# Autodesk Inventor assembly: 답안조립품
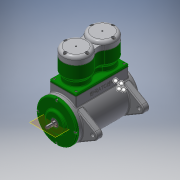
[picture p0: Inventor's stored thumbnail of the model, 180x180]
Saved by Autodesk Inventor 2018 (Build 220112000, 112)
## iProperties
Created: 2019-08
Part Number: 답안조립품
Document SubType Name: Assembly
Designer: Administrator
Mass: 7632.99 g
Surface Area: 5241.59 cm^2
Volume: 2149.87 cm^3
Density: 3.55045 g/cm^3
Author: Administrator
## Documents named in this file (18)
- C:\Users\Administrator\Desktop\1\답안조립품.iam
- C:\Users\Administrator\Desktop\1\본체.ipt
- C:\Users\Administrator\Desktop\1\실린더 개스킷.ipt
- C:\Users\Administrator\Desktop\1\실린더.ipt
- C:\Users\Administrator\Desktop\1\실린더헤드 개스킷.ipt
- C:\Users\Administrator\Desktop\1\실린더헤드.ipt
- C:\Users\Administrator\Desktop\1\볼트 M4 x 8.ipt
- C:\Users\Administrator\Desktop\1\볼트 M5 x 20.ipt
- C:\Users\Administrator\Desktop\1\너트 M4.ipt
- C:\Users\Administrator\Desktop\1\육각 머리 볼트 M4 x 16.ipt
- C:\Users\Administrator\Desktop\1\커넥팅로드.ipt
- C:\Users\Administrator\Desktop\1\피스톤.ipt
- C:\Users\Administrator\Desktop\1\피스톤핀.ipt
- C:\Users\Administrator\Desktop\1\커넥팅로드 엔드.ipt
- C:\Users\Administrator\Desktop\1\베어링 12 x 28 x 8.ipt
- C:\Users\Administrator\Desktop\1\앞커버.ipt
- C:\Users\Administrator\Desktop\1\오일 실 12 25 7.ipt
- C:\Users\Administrator\Desktop\1\크랭크축.ipt
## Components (4 placed, 2 different names)
1. 피스톤:1
2. 피스톤핀:1
3. 피스톤:2
4. 피스톤핀:2
## Named parameters: d47_d38 = 0, d48_d39 = 0, d49_d40 = 0, d50_d41 = 0, d51_d42 = 0, d52_d44 = 0, d53_d45 = 0, d54_d46 = 0, d55_d32 = 0, d56_d33 = 0, d57_d34 = 0, d58_d35 = 0, d59_d36 = 0, d60_d37 = 0
